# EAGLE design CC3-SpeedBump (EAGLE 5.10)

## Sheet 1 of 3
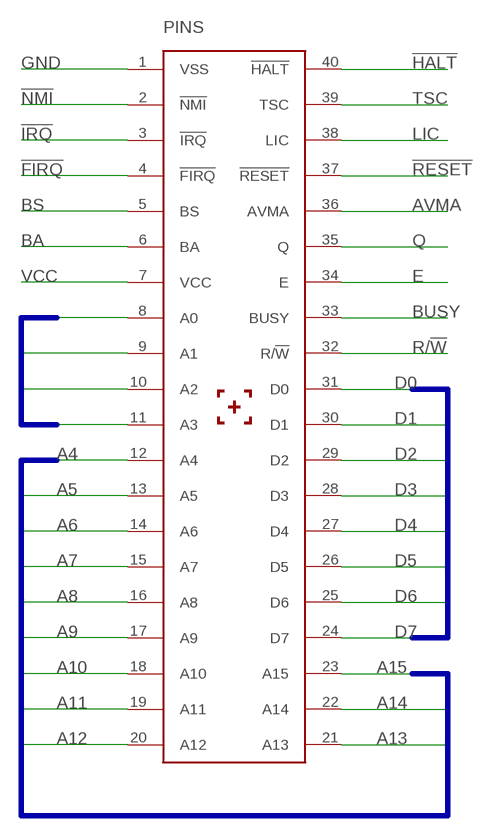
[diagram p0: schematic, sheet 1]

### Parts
PINS  6809E-ISOLATED-VCC-GNDNT-MSPL20  [DIL40-6-MACHINED-SOCKET-PINS-LAYER20OUTLINE]

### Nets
!FIRQ: PINS.4(!FIRQ) ; also sheet 2
!HALT: PINS.40(!HALT) ; also sheet 2
!IRQ: PINS.3(!IRQ) ; also sheet 2
!NMI: PINS.2(!NMI) ; also sheet 2
!RESET: PINS.37(!RESET) ; also sheet 2
A4: PINS.12(A4) ; also sheet 2,3
A5: PINS.13(A5) ; also sheet 2,3
A6: PINS.14(A6) ; also sheet 2,3
A7: PINS.15(A7) ; also sheet 2,3
A8: PINS.16(A8) ; also sheet 2,3
A9: PINS.17(A9) ; also sheet 2,3
A10: PINS.18(A10) ; also sheet 2,3
A11: PINS.19(A11) ; also sheet 2,3
A12: PINS.20(A12) ; also sheet 2,3
A13: PINS.21(A13) ; also sheet 2,3
A14: PINS.22(A14) ; also sheet 2,3
A15: PINS.23(A15) ; also sheet 2,3
AVMA: PINS.36(AVMA) ; also sheet 2
BA: PINS.6(BA) ; also sheet 2
BA0: PINS.8(A0) ; also sheet 3
BA1: PINS.9(A1) ; also sheet 3
BA2: PINS.10(A2) ; also sheet 3
BA3: PINS.11(A3) ; also sheet 3
BS: PINS.5(BS) ; also sheet 2
BUSY: PINS.33(BUSY) ; also sheet 2
D0: PINS.31(D0) ; also sheet 2
D1: PINS.30(D1) ; also sheet 2
D2: PINS.29(D2) ; also sheet 2
D3: PINS.28(D3) ; also sheet 2
D4: PINS.27(D4) ; also sheet 2
D5: PINS.26(D5) ; also sheet 2
D6: PINS.25(D6) ; also sheet 2
D7: PINS.24(D7) ; also sheet 2
E: PINS.34(E) ; also sheet 2
GND [power]: PINS.1(VSS) ; also sheet 2,3
LIC: PINS.38(LIC) ; also sheet 2
Q: PINS.35(Q) ; also sheet 2
R/!W: PINS.32(R/!W) ; also sheet 2
TSC: PINS.39(TSC) ; also sheet 2
VCC [power]: PINS.7(VCC) ; also sheet 2,3

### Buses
A[0..15]
BA[0..3]
D[0..7]

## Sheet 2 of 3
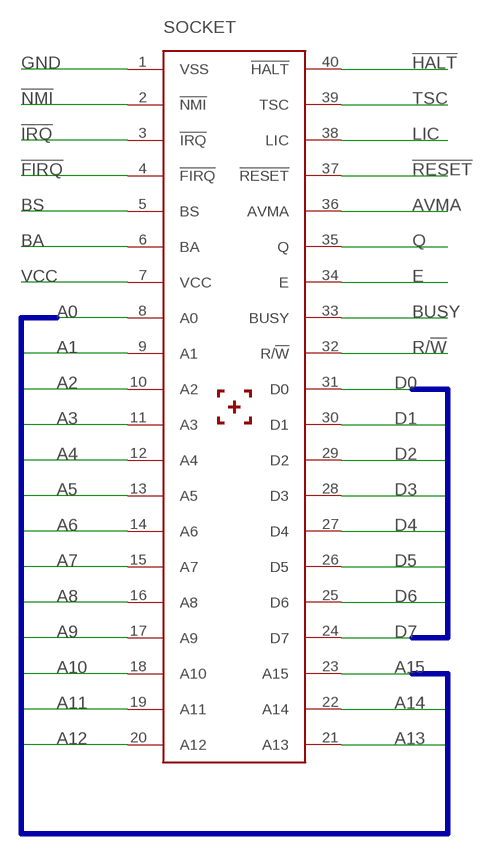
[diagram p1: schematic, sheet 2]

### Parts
SOCKET  6809E-ISOLATED-VCC-GNDNT-RHPS1  [DIL40-6-ROUND-HEADER-PINS-STAGGERED-1]

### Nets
!FIRQ: SOCKET.4(!FIRQ) ; also sheet 1
!HALT: SOCKET.40(!HALT) ; also sheet 1
!IRQ: SOCKET.3(!IRQ) ; also sheet 1
!NMI: SOCKET.2(!NMI) ; also sheet 1
!RESET: SOCKET.37(!RESET) ; also sheet 1
A0: SOCKET.8(A0) ; also sheet 3
A1: SOCKET.9(A1) ; also sheet 3
A2: SOCKET.10(A2) ; also sheet 3
A3: SOCKET.11(A3) ; also sheet 3
A4: SOCKET.12(A4) ; also sheet 1,3
A5: SOCKET.13(A5) ; also sheet 1,3
A6: SOCKET.14(A6) ; also sheet 1,3
A7: SOCKET.15(A7) ; also sheet 1,3
A8: SOCKET.16(A8) ; also sheet 1,3
A9: SOCKET.17(A9) ; also sheet 1,3
A10: SOCKET.18(A10) ; also sheet 1,3
A11: SOCKET.19(A11) ; also sheet 1,3
A12: SOCKET.20(A12) ; also sheet 1,3
A13: SOCKET.21(A13) ; also sheet 1,3
A14: SOCKET.22(A14) ; also sheet 1,3
A15: SOCKET.23(A15) ; also sheet 1,3
AVMA: SOCKET.36(AVMA) ; also sheet 1
BA: SOCKET.6(BA) ; also sheet 1
BS: SOCKET.5(BS) ; also sheet 1
BUSY: SOCKET.33(BUSY) ; also sheet 1
D0: SOCKET.31(D0) ; also sheet 1
D1: SOCKET.30(D1) ; also sheet 1
D2: SOCKET.29(D2) ; also sheet 1
D3: SOCKET.28(D3) ; also sheet 1
D4: SOCKET.27(D4) ; also sheet 1
D5: SOCKET.26(D5) ; also sheet 1
D6: SOCKET.25(D6) ; also sheet 1
D7: SOCKET.24(D7) ; also sheet 1
E: SOCKET.34(E) ; also sheet 1
GND [power]: SOCKET.1(VSS) ; also sheet 1,3
LIC: SOCKET.38(LIC) ; also sheet 1
Q: SOCKET.35(Q) ; also sheet 1
R/!W: SOCKET.32(R/!W) ; also sheet 1
TSC: SOCKET.39(TSC) ; also sheet 1
VCC [power]: SOCKET.7(VCC) ; also sheet 1,3

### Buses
A[0..15]
D[0..7]

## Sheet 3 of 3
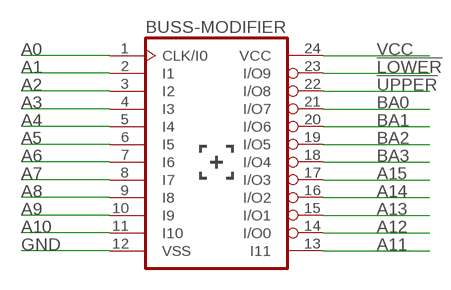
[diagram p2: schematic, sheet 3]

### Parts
BUSS-MODIFIER  GAL22V10N-TMO1S  [DIL24-3-TOP-MINIMAL-OUTLINE-1-STAGGERED]

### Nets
!LOWER: BUSS-MODIFIER.23(I/O9)
!UPPER: BUSS-MODIFIER.22(I/O8)
A0: BUSS-MODIFIER.1(CLK/I0) ; also sheet 2
A1: BUSS-MODIFIER.2(I1) ; also sheet 2
A2: BUSS-MODIFIER.3(I2) ; also sheet 2
A3: BUSS-MODIFIER.4(I3) ; also sheet 2
A4: BUSS-MODIFIER.5(I4) ; also sheet 1,2
A5: BUSS-MODIFIER.6(I5) ; also sheet 1,2
A6: BUSS-MODIFIER.7(I6) ; also sheet 1,2
A7: BUSS-MODIFIER.8(I7) ; also sheet 1,2
A8: BUSS-MODIFIER.9(I8) ; also sheet 1,2
A9: BUSS-MODIFIER.10(I9) ; also sheet 1,2
A10: BUSS-MODIFIER.11(I10) ; also sheet 1,2
A11: BUSS-MODIFIER.13(I11) ; also sheet 1,2
A12: BUSS-MODIFIER.14(I/O0) ; also sheet 1,2
A13: BUSS-MODIFIER.15(I/O1) ; also sheet 1,2
A14: BUSS-MODIFIER.16(I/O2) ; also sheet 1,2
A15: BUSS-MODIFIER.17(I/O3) ; also sheet 1,2
BA0: BUSS-MODIFIER.21(I/O7) ; also sheet 1
BA1: BUSS-MODIFIER.20(I/O6) ; also sheet 1
BA2: BUSS-MODIFIER.19(I/O5) ; also sheet 1
BA3: BUSS-MODIFIER.18(I/O4) ; also sheet 1
GND [power]: BUSS-MODIFIER.12(VSS) ; also sheet 1,2
VCC [power]: BUSS-MODIFIER.24(VCC) ; also sheet 1,2

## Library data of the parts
BUSS-MODIFIER = TCADT-CoCo-3-SpeedBump-03-30-1987:GAL22V10
PINS SOCKET = TCADT-CoCo-3-SpeedBump-03-30-1987:6809E-ISOLATED-VCC-GND: 6809E Microprocessor 6809E Microprocessor References: http://www.classiccmp.org/dunfield/r/6809e.pdf https://web.archive.org/web/20170220210936/http://www.classiccmp.org/dunfield/r/6809e.pdf Copyright &copy;10 May 2017, by: Tin Cans And Duct Tape, LLC All Rights Reserved. http://www.TCADT.com/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

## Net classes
0 default: width 0.203 mm, clearance 0.152 mm
1 power: width 0.762 mm, clearance 0.152 mm

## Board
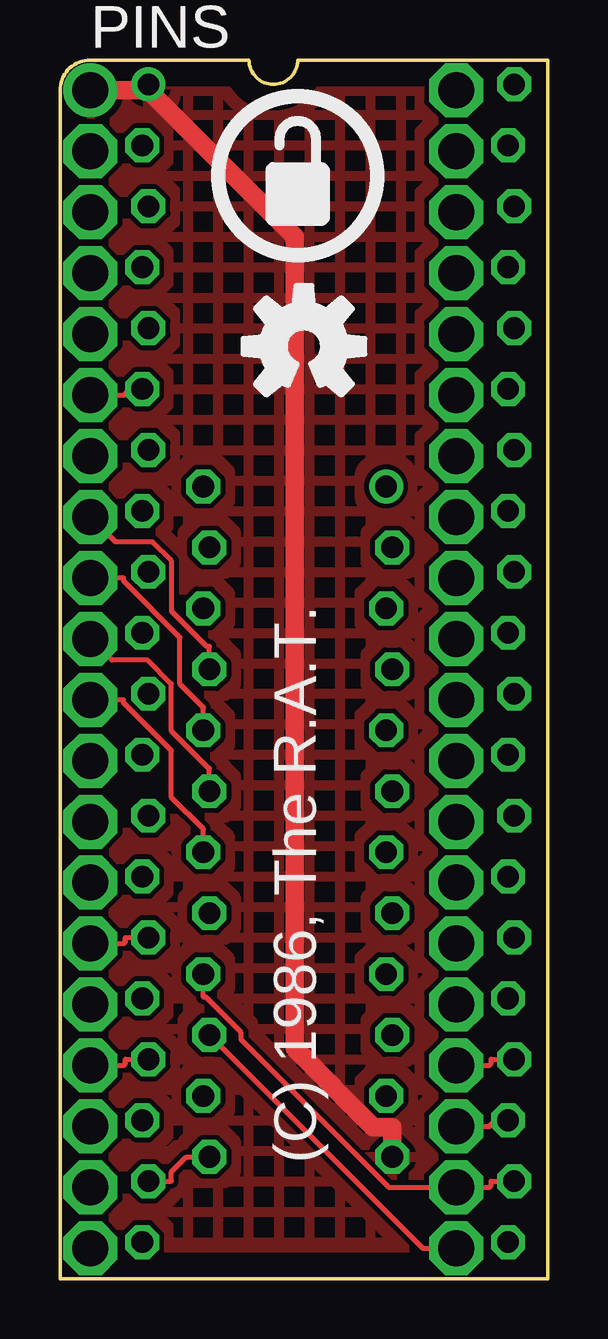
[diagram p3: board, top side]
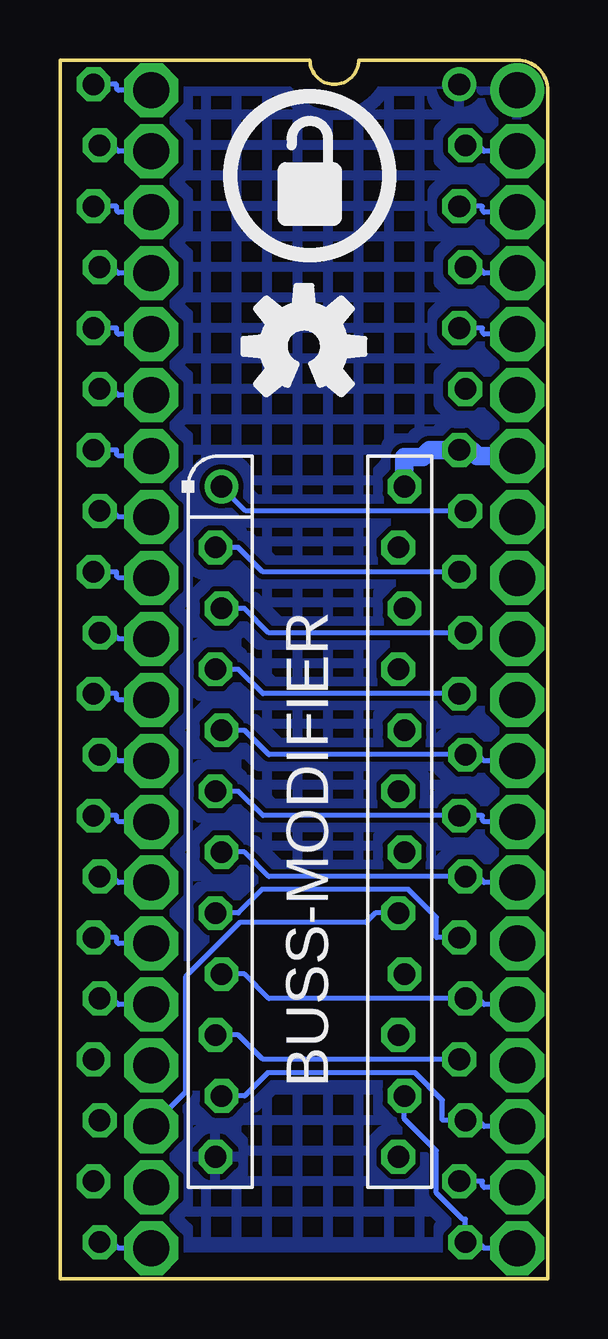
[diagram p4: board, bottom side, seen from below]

Size 20.32 x 50.8 mm. Coordinates in mm from the lower left corner, seen from the top.
Copper layers (1*16): Top 0.035mm / dielectric 1.5mm / Bottom 0.035mm
Design rules "default": minimum track width 10mil, minimum drill 24mil, track to track 8mil, track to pad 8mil, pad to pad 8mil, via to via 8mil, smd to smd 8mil, copper to edge 40mil, drill to drill 8mil, minimum pad ring 10mil, minimum via ring 8mil, stop-mask expansion 4mil, vias tented up to drill 0mil, thermal gap 10mil

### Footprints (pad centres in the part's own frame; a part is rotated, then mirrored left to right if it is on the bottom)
DIL24-3-TOP-MINIMAL-OUTLINE-1-STAGGERED = drill 0.9 round: 1 -13.97,-3.683 | drill 0.9 octagon: 2 -11.43,-3.937; 3 -8.89,-3.683; 4 -6.35,-3.937; 5 -3.81,-3.683; 6 -1.27,-3.937; 7 1.27,-3.683; 8 3.81,-3.937; 9 6.35,-3.683; 10 8.89,-3.937; 11 11.43,-3.683; 12 13.97,-3.937; 13 13.97,3.683; 14 11.43,3.937; 15 8.89,3.683; 16 6.35,3.937; 17 3.81,3.683; 18 1.27,3.937; 19 -1.27,3.683; 20 -3.81,3.937; 21 -6.35,3.683; 22 -8.89,3.937; 23 -11.43,3.683; 24 -13.97,3.937
DIL40-6-MACHINED-SOCKET-PINS-LAYER20OUTLINE = drill 1.5 round: 1 -24.13,-7.62 | drill 1.5 octagon: 2 -21.59,-7.62; 3 -19.05,-7.62; 4 -16.51,-7.62; 5 -13.97,-7.62; 6 -11.43,-7.62; 7 -8.89,-7.62; 8 -6.35,-7.62; 9 -3.81,-7.62; 10 -1.27,-7.62; 11 1.27,-7.62; 12 3.81,-7.62; 13 6.35,-7.62; 14 8.89,-7.62; 15 11.43,-7.62; 16 13.97,-7.62; 17 16.51,-7.62; 18 19.05,-7.62; 19 21.59,-7.62; 20 24.13,-7.62; 21 24.13,7.62; 22 21.59,7.62; 23 19.05,7.62; 24 16.51,7.62; 25 13.97,7.62; 26 11.43,7.62; 27 8.89,7.62; 28 6.35,7.62; 29 3.81,7.62; 30 1.27,7.62; 31 -1.27,7.62; 32 -3.81,7.62; 33 -6.35,7.62; 34 -8.89,7.62; 35 -11.43,7.62; 36 -13.97,7.62; 37 -16.51,7.62; 38 -19.05,7.62; 39 -21.59,7.62; 40 -24.13,7.62
DIL40-6-ROUND-HEADER-PINS-STAGGERED-1 = drill 0.9 round: 1 -24.13,-7.493 | drill 0.9 octagon: 2 -21.59,-7.747; 3 -19.05,-7.493; 4 -16.51,-7.747; 5 -13.97,-7.493; 6 -11.43,-7.747; 7 -8.89,-7.493; 8 -6.35,-7.747; 9 -3.81,-7.493; 10 -1.27,-7.747; 11 1.27,-7.493; 12 3.81,-7.747; 13 6.35,-7.493; 14 8.89,-7.747; 15 11.43,-7.493; 16 13.97,-7.747; 17 16.51,-7.493; 18 19.05,-7.747; 19 21.59,-7.493; 20 24.13,-7.747; 21 24.13,7.493; 22 21.59,7.747; 23 19.05,7.493; 24 16.51,7.747; 25 13.97,7.493; 26 11.43,7.747; 27 8.89,7.493; 28 6.35,7.747; 29 3.81,7.493; 30 1.27,7.747; 31 -1.27,7.493; 32 -3.81,7.747; 33 -6.35,7.493; 34 -8.89,7.747; 35 -11.43,7.493; 36 -13.97,7.747; 37 -16.51,7.493; 38 -19.05,7.747; 39 -21.59,7.493; 40 -24.13,7.747

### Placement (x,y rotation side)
BUSS-MODIFIER  9.91,19.05 270 bottom
PINS  8.89,25.4 270 top
SOCKET  11.18,25.65 270 top
U$1  [OSHWLOGO_0.3]  9.91,45.97 0 top
U$2  [OSHWLOGO_0.3]  9.91,45.97 0 bottom
U$3  [OSHWLOGO_TOL_0.2]  10.16,38.86 0 top
U$4  [OSHWLOGO_TOL_0.2]  10.16,38.86 0 bottom

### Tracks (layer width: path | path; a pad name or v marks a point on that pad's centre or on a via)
!FIRQ
  Bottom 0.203: PINS.4 2.65,41.91 2.9,42.16 SOCKET.4
!HALT
  Bottom 0.203: SOCKET.40 17.97,49.78 17.97,49.61 17.89,49.53 PINS.40
!IRQ
  Bottom 0.203: SOCKET.3 2.73,44.7 2.73,44.53 2.65,44.45 PINS.3
!NMI
  Bottom 0.203: PINS.2 2.65,46.99 2.9,47.24 SOCKET.2
!RESET
  Bottom 0.203: PINS.37 17.89,41.91 18.14,42.16 SOCKET.37
A0
  Bottom 0.203: SOCKET.8 12.57,32 BUSS-MODIFIER.1
A1
  Bottom 0.203: BUSS-MODIFIER.2 12.88,30.48 11.87,29.46 SOCKET.9
A2
  Bottom 0.203: BUSS-MODIFIER.3 12.63,27.94 11.62,26.92 SOCKET.10
A3
  Bottom 0.203: BUSS-MODIFIER.4 12.88,25.4 11.87,24.38 SOCKET.11
A4
  Bottom 0.203: BUSS-MODIFIER.5 12.63,22.86 11.62,21.84 SOCKET.12 2.9,21.84 2.65,21.59 PINS.12
A5
  Bottom 0.203: PINS.13 2.65,19.05 2.73,19.13 2.73,19.3 SOCKET.13 11.87,19.3 12.88,20.32 BUSS-MODIFIER.6
A6
  Bottom 0.203: BUSS-MODIFIER.7 12.63,17.78 11.62,16.76 SOCKET.14 2.9,16.76 2.65,16.51 PINS.14
A7
  Top 0.203: SOCKET.15 2.73,14.22 2.73,14.05 2.65,13.97 PINS.15
  Bottom 0.203: BUSS-MODIFIER.8 12.88,15.24 11.9,16.23 5.81,16.23 4.64,15.06 4.64,14.22 SOCKET.15
A8
  Bottom 0.203: BUSS-MODIFIER.9 12.63,12.7 11.62,11.68 SOCKET.16 2.9,11.68 2.65,11.43 PINS.16
A9
  Top 0.203: SOCKET.17 2.73,9.14 2.73,8.97 2.65,8.89 PINS.17
  Bottom 0.203: BUSS-MODIFIER.10 12.88,10.16 11.87,9.14 SOCKET.17
A10
  Bottom 0.203: BUSS-MODIFIER.11 12.63,7.62 11.67,8.58 5.53,8.58 4.39,7.44 4.39,6.6 SOCKET.18 2.9,6.6 2.65,6.35 PINS.18
A11
  Top 0.203: SOCKET.19 4.64,4.06 4.64,4.46 5.26,5.08 BUSS-MODIFIER.13
  Bottom 0.203: SOCKET.19 2.73,4.06 2.73,3.89 2.65,3.81 PINS.19
A12
  Bottom 0.203: BUSS-MODIFIER.14 5.97,6.66 4.64,5.33 4.64,3.57 3.55,2.48 3.43,2.48 SOCKET.20 2.9,1.52 2.65,1.27 PINS.20
A13
  Top 0.203: PINS.21 15.11,1.27 BUSS-MODIFIER.15
  Bottom 0.203: PINS.21 17.89,1.27 18.14,1.52 SOCKET.21
A14
  Top 0.203: SOCKET.22 17.97,4.06 17.97,3.89 17.89,3.81 PINS.22 13.7,3.81 7.55,9.96 7.55,10.26 6.07,11.74 5.97,11.74 BUSS-MODIFIER.16
A15
  Top 0.203: PINS.23 17.89,6.35 18.14,6.6 SOCKET.23
  Bottom 0.203: BUSS-MODIFIER.17 7.18,15.24 7.58,14.84 12.83,14.84 15.1,12.58 15.1,7.76 PINS.23
AVMA
  Bottom 0.203: SOCKET.36 17.97,39.62 17.97,39.45 17.89,39.37 PINS.36
BA
  Top 0.203: PINS.6 2.65,36.83 2.9,37.08 SOCKET.6
BA0
  Top 0.203: BUSS-MODIFIER.21 6.22,26.36 6.11,26.36 4.65,27.82 4.65,29.91 3.85,30.71 2.31,30.71 PINS.8
BA1
  Top 0.203: BUSS-MODIFIER.20 5.97,23.82 5,24.79 5,26.74 2.65,29.08 2.65,29.21 PINS.9
BA2
  Top 0.203: BUSS-MODIFIER.19 6.22,21.28 6.2,21.28 4.64,22.83 4.64,24.8 3.66,25.78 2.16,25.78 PINS.10
BA3
  Top 0.203: BUSS-MODIFIER.18 5.97,18.74 4.64,20.07 4.64,22.01 2.65,24 2.65,24.13 PINS.11
BS
  Bottom 0.203: SOCKET.5 2.73,39.62 2.73,39.45 2.65,39.37 PINS.5
BUSY
  Bottom 0.203: PINS.33 17.89,31.75 18.14,32 SOCKET.33
D0
  Bottom 0.203: PINS.31 17.89,26.67 18.14,26.92 SOCKET.31
D1
  Bottom 0.203: SOCKET.30 17.97,24.38 17.97,24.21 17.89,24.13 PINS.30
D2
  Bottom 0.203: PINS.29 17.89,21.59 18.14,21.84 SOCKET.29
D3
  Bottom 0.203: SOCKET.28 17.97,19.3 17.97,19.13 17.89,19.05 PINS.28
D4
  Bottom 0.203: PINS.27 17.89,16.51 18.14,16.76 SOCKET.27
D5
  Bottom 0.203: SOCKET.26 17.97,14.22 17.97,14.05 17.89,13.97 PINS.26
D6
  Bottom 0.203: PINS.25 17.89,11.43 18.14,11.68 SOCKET.25
D7
  Top 0.203: SOCKET.24 17.97,9.14 17.97,8.97 17.89,8.89 PINS.24
E
  Bottom 0.203: SOCKET.34 17.97,34.54 17.97,34.37 17.89,34.29 PINS.34
GND
  Top 0.762: 3.68,49.53 9.78,43.43 9.78,9.6 13.06,6.32 13.84,6.32 BUSS-MODIFIER.12 | 3.68,49.53 SOCKET.1 | 3.68,49.53 PINS.1
  pour Bottom (hatched): -0.51,51.56 20.83,51.56 20.83,-0.76 -0.51,-0.76
  pour Top (hatched): -0.76,51.82 21.08,51.82 21.08,-0.76 -0.76,-0.76
LIC
  Bottom 0.203: SOCKET.38 17.97,44.7 17.97,44.53 17.89,44.45 PINS.38
Q
  Bottom 0.203: PINS.35 17.89,36.83 18.14,37.08 SOCKET.35
R/!W
  Bottom 0.203: SOCKET.32 17.97,29.46 17.97,29.29 17.89,29.21 PINS.32
TSC
  Bottom 0.203: PINS.39 17.89,46.99 18.14,47.24 SOCKET.39
VCC
  Bottom 0.762: BUSS-MODIFIER.24 5.97,34.26 5.21,34.26 4.92,34.54 SOCKET.7 3.18,34.54 2.93,34.29 PINS.7

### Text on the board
tPlace: (C) 1986, The R.A.T.
Reference: The 22V10 mounts on the solder side. | Use a low profile IC Socket. | The large holes are for socket pins | liberated from machined pin I.C. sockets. | Use the LONGEST you can find. | These become the pins that plug | into the CPU Socket. The small | holes are for the new CPU Socket.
